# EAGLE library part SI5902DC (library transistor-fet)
Dual N-Channel 30-V (D-S) MOSFET Source: http://www.vishay.com/docs/71053/71053.pdf
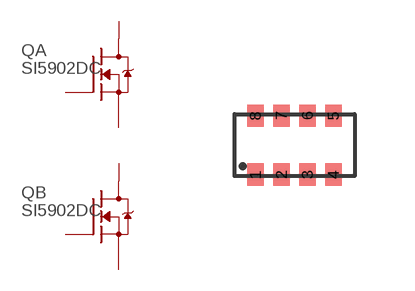
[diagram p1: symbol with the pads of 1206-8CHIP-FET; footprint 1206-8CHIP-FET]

Designator prefix Q; gates A=N-MOSFET-G2DS-D B=N-MOSFET-G2DS-D

## SI5902DC  [1206-8CHIP-FET]
1  A:S  pas
2  A:G  pas
3  B:S  pas
4  B:G  pas
5  B:D  pas
6  B:D1  pas
7  A:D1  pas
8  A:D  pas

## Footprint 1206-8CHIP-FET (pad centres in mm)
1206-8 ChipFET Source: http://www.vishay.com/docs/72593/72593.pdf http://www.vishay.com/docs/71151/71151.pdf
smd 0.406 x 0.56: 1 -0.975,-0.737; 2 -0.325,-0.737; 3 0.325,-0.737; 4 0.975,-0.737; 5 0.975,0.737; 6 0.325,0.737; 7 -0.325,0.737; 8 -0.975,0.737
